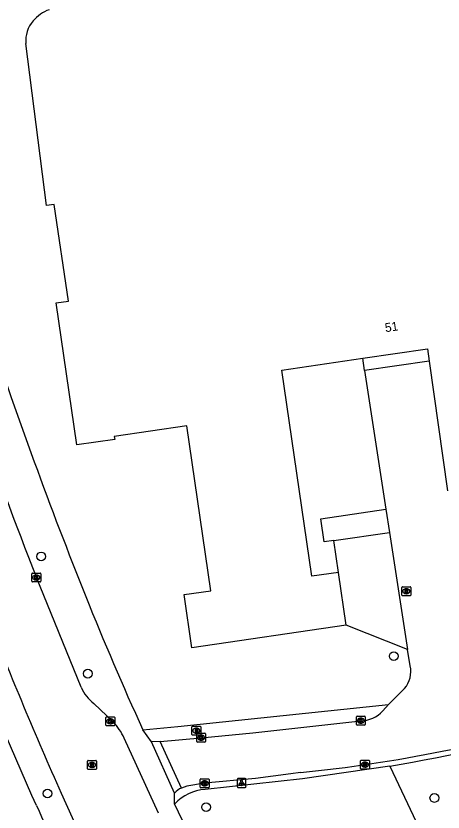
# Model space of a CAD drawing. Extents: x 159503 to 160347, y 382525 to 383272.
# Drawn here: x 159637.5 to 159685.5, y 382615.1 to 382704.5 of the extents above; entities that cross this region are included whole.
import ezdxf

# ---------------------------------------------------------------- set-up
doc = ezdxf.new("R2010")
doc.units = 0
for name, color, linetype in [('IMGEO_Boom', 7, 'Continuous'), ('IMGEO_Brandkraan', 7, 'Continuous'), ('IMGEO_Groenvoorziening', 7, 'Continuous'), ('IMGEO_Kolk', 7, 'Continuous'), ('IMGEO_Lichtpunt', 7, 'Continuous'), ('IMGEO_Pand', 7, 'Continuous'), ('IMGEO_Pand_nummerreeks', 7, 'Continuous'), ('IMGEO_Parkeervlak_open', 7, 'Continuous'), ('IMGEO_Rijbaan_lokaal_open', 7, 'Continuous'), ('IMGEO_Rijbaan_regionaal_gesloten', 7, 'Continuous'), ('IMGEO_Rioolput', 7, 'Continuous'), ('IMGEO_Voetpad_open', 7, 'Continuous')]:
    doc.layers.add(name, color=color, linetype=linetype)

msp = doc.modelspace()

# ---------------------------------------------------------------- linework, layer by layer
at = {"layer": 'IMGEO_Boom'}
for centre in [(159640.39, 382643.791), (159679.978, 382632.569), (159645.632, 382630.613), (159641.094, 382617.148), (159684.542, 382616.644), (159658.898, 382615.617)]:
    msp.add_circle(centre, 0.489, dxfattribs=at)
at = {"layer": 'IMGEO_Brandkraan'}
for p, q in [((159657.311, 382623.78), (159657.311, 382624.632)), ((159657.386, 382624.706), (159658.238, 382624.706)), ((159657.799, 382624.486), (159657.824, 382624.486)), ((159658.312, 382624.632), (159658.312, 382623.78)), ((159658.238, 382623.706), (159657.386, 382623.706)), ((159657.822, 382623.926), (159657.797, 382623.926))]:
    msp.add_line(p, q, dxfattribs=at)
for points in [[(159657.311, 382623.78), (159657.311, 382624.632)], [(159657.386, 382624.706), (159658.238, 382624.706)], [(159657.659, 382624.406), (159657.659, 382624.006), (159657.872, 382624.006)], [(159657.89, 382624.406), (159657.659, 382624.406)], [(159658.312, 382624.632), (159658.312, 382623.78)], [(159658.238, 382623.706), (159657.386, 382623.706)], [(159657.838, 382624.325), (159657.784, 382624.325), (159657.784, 382624.249)], [(159657.784, 382624.249), (159657.837, 382624.249)], [(159657.846, 382624.173), (159657.784, 382624.173), (159657.784, 382624.092)], [(159657.784, 382624.092), (159657.846, 382624.092)]]:
    msp.add_lwpolyline(points, dxfattribs=at)
for centre, radius, start, end in [((159657.388, 382624.63), 0.0765, 91.55205, 178.44795), ((159657.388, 382624.63), 0.0765, 91.55205, 178.44795), ((159657.894, 382624.261), 0.145, 59.4692, 91.53667), ((159657.919, 382624.308), 0.0922, 285.51372, 58.15012), ((159658.236, 382624.63), 0.0765, 1.55205, 88.44795), ((159658.236, 382624.63), 0.0765, 1.55205, 88.44795), ((159657.388, 382623.782), 0.0765, 181.55205, 268.44795), ((159657.388, 382623.782), 0.0765, 181.55205, 268.44795), ((159657.839, 382624.287), 0.0379, 267.82845, 90.93552), ((159657.847, 382624.132), 0.0404, 269.87594, 90.50774), ((159657.878, 382624.257), 0.251, 268.66757, 293.53466), ((159657.924, 382624.116), 0.105, 301.31148, 78.98903), ((159658.236, 382623.782), 0.0765, 271.55205, 358.44795), ((159658.236, 382623.782), 0.0765, 271.55205, 358.44795)]:
    msp.add_arc(centre, radius, start, end, dxfattribs=at)
for centre, major_axis, ratio, start_param, end_param in [((159657.798, 382624.206), (-0.387, 0.002), 0.722429, 4.712389, 7.853982), ((159657.823, 382624.206), (-0.39, 0.002), 0.717154, 1.570796, 4.712389)]:
    msp.add_ellipse(centre, major_axis=major_axis, ratio=ratio, start_param=start_param, end_param=end_param, dxfattribs=at)
at = {"layer": 'IMGEO_Groenvoorziening'}
msp.add_lwpolyline([(159679.532, 382620.228), (159692.346, 382593.146)], dxfattribs=at)
at = {"layer": 'IMGEO_Kolk'}
for p, q in [((159639.342, 382640.986), (159639.342, 382641.838)), ((159639.417, 382641.912), (159640.269, 382641.912)), ((159639.83, 382641.692), (159639.855, 382641.692)), ((159640.343, 382641.838), (159640.343, 382640.986)), ((159640.269, 382640.912), (159639.417, 382640.912)), ((159639.853, 382641.132), (159639.828, 382641.132)), ((159647.643, 382624.838), (159647.643, 382625.69)), ((159647.718, 382625.764), (159648.57, 382625.764)), ((159648.131, 382625.544), (159648.156, 382625.544)), ((159648.644, 382625.69), (159648.644, 382624.838)), ((159675.781, 382624.903), (159675.781, 382625.755)), ((159675.856, 382625.829), (159676.708, 382625.829)), ((159676.269, 382625.609), (159676.294, 382625.609)), ((159676.782, 382625.755), (159676.782, 382624.903)), ((159648.57, 382624.764), (159647.718, 382624.764)), ((159648.154, 382624.984), (159648.129, 382624.984)), ((159676.708, 382624.829), (159675.856, 382624.829)), ((159676.292, 382625.049), (159676.267, 382625.049)), ((159657.851, 382622.989), (159657.851, 382623.841)), ((159657.926, 382623.915), (159658.778, 382623.915)), ((159658.339, 382623.695), (159658.364, 382623.695)), ((159658.852, 382623.841), (159658.852, 382622.989)), ((159658.778, 382622.915), (159657.926, 382622.915)), ((159658.362, 382623.135), (159658.337, 382623.135)), ((159676.249, 382619.969), (159676.249, 382620.821)), ((159676.324, 382620.895), (159677.176, 382620.895)), ((159677.25, 382620.821), (159677.25, 382619.969)), ((159676.76, 382620.115), (159676.735, 382620.115)), ((159676.737, 382620.675), (159676.762, 382620.675)), ((159677.176, 382619.895), (159676.324, 382619.895)), ((159658.234, 382617.865), (159658.234, 382618.717)), ((159658.309, 382618.791), (159659.161, 382618.791)), ((159658.722, 382618.571), (159658.747, 382618.571)), ((159659.235, 382618.717), (159659.235, 382617.865)), ((159659.161, 382617.791), (159658.309, 382617.791)), ((159658.745, 382618.011), (159658.72, 382618.011))]:
    msp.add_line(p, q, dxfattribs=at)
for points in [[(159639.342, 382640.986), (159639.342, 382641.838)], [(159639.417, 382641.912), (159640.269, 382641.912)], [(159639.663, 382641.612), (159639.786, 382641.612), (159639.786, 382641.461), (159639.916, 382641.612), (159640.08, 382641.612), (159639.934, 382641.461), (159640.087, 382641.212), (159639.935, 382641.212), (159639.85, 382641.376), (159639.786, 382641.309), (159639.786, 382641.212), (159639.663, 382641.212), (159639.663, 382641.612)], [(159640.343, 382641.838), (159640.343, 382640.986)], [(159640.269, 382640.912), (159639.417, 382640.912)], [(159647.643, 382624.838), (159647.643, 382625.69)], [(159647.718, 382625.764), (159648.57, 382625.764)], [(159647.964, 382625.464), (159648.087, 382625.464), (159648.087, 382625.313), (159648.217, 382625.464), (159648.381, 382625.464), (159648.235, 382625.313), (159648.388, 382625.064), (159648.236, 382625.064), (159648.151, 382625.228), (159648.087, 382625.161), (159648.087, 382625.064), (159647.964, 382625.064), (159647.964, 382625.464)], [(159648.644, 382625.69), (159648.644, 382624.838)], [(159675.781, 382624.903), (159675.781, 382625.755)], [(159675.856, 382625.829), (159676.708, 382625.829)], [(159676.102, 382625.529), (159676.225, 382625.529), (159676.225, 382625.378), (159676.355, 382625.529), (159676.519, 382625.529), (159676.373, 382625.378), (159676.526, 382625.129), (159676.374, 382625.129), (159676.289, 382625.293), (159676.225, 382625.226), (159676.225, 382625.129), (159676.102, 382625.129), (159676.102, 382625.529)], [(159676.782, 382625.755), (159676.782, 382624.903)], [(159648.57, 382624.764), (159647.718, 382624.764)], [(159676.708, 382624.829), (159675.856, 382624.829)], [(159657.851, 382622.989), (159657.851, 382623.841)], [(159657.926, 382623.915), (159658.778, 382623.915)], [(159658.172, 382623.615), (159658.295, 382623.615), (159658.295, 382623.464), (159658.425, 382623.615), (159658.589, 382623.615), (159658.443, 382623.464), (159658.596, 382623.215), (159658.444, 382623.215), (159658.359, 382623.379), (159658.295, 382623.312), (159658.295, 382623.215), (159658.172, 382623.215), (159658.172, 382623.615)], [(159658.852, 382623.841), (159658.852, 382622.989)], [(159658.778, 382622.915), (159657.926, 382622.915)], [(159676.249, 382619.969), (159676.249, 382620.821)], [(159676.324, 382620.895), (159677.176, 382620.895)], [(159677.25, 382620.821), (159677.25, 382619.969)], [(159676.57, 382620.595), (159676.693, 382620.595), (159676.693, 382620.444), (159676.823, 382620.595), (159676.987, 382620.595), (159676.841, 382620.444), (159676.994, 382620.195), (159676.842, 382620.195), (159676.757, 382620.359), (159676.693, 382620.292), (159676.693, 382620.195), (159676.57, 382620.195), (159676.57, 382620.595)], [(159677.176, 382619.895), (159676.324, 382619.895)], [(159658.234, 382617.865), (159658.234, 382618.717)], [(159658.309, 382618.791), (159659.161, 382618.791)], [(159658.555, 382618.491), (159658.678, 382618.491), (159658.678, 382618.34), (159658.808, 382618.491), (159658.972, 382618.491), (159658.826, 382618.34), (159658.979, 382618.091), (159658.827, 382618.091), (159658.742, 382618.255), (159658.678, 382618.188), (159658.678, 382618.091), (159658.555, 382618.091), (159658.555, 382618.491)], [(159659.235, 382618.717), (159659.235, 382617.865)], [(159659.161, 382617.791), (159658.309, 382617.791)]]:
    msp.add_lwpolyline(points, dxfattribs=at)
for centre, start, end in [((159639.419, 382641.836), 91.55205, 178.44795), ((159639.419, 382641.836), 91.55205, 178.44795), ((159640.267, 382641.836), 1.55205, 88.44795), ((159640.267, 382641.836), 1.55205, 88.44795), ((159639.419, 382640.988), 181.55205, 268.44795), ((159639.419, 382640.988), 181.55205, 268.44795), ((159640.267, 382640.988), 271.55205, 358.44795), ((159640.267, 382640.988), 271.55205, 358.44795), ((159647.72, 382625.688), 91.55205, 178.44795), ((159647.72, 382625.688), 91.55205, 178.44795), ((159648.568, 382625.688), 1.55205, 88.44795), ((159648.568, 382625.688), 1.55205, 88.44795), ((159675.858, 382625.753), 91.55205, 178.44795), ((159675.858, 382625.753), 91.55205, 178.44795), ((159676.706, 382625.753), 1.55205, 88.44795), ((159676.706, 382625.753), 1.55205, 88.44795), ((159647.72, 382624.84), 181.55205, 268.44795), ((159647.72, 382624.84), 181.55205, 268.44795), ((159648.568, 382624.84), 271.55205, 358.44795), ((159648.568, 382624.84), 271.55205, 358.44795), ((159675.858, 382624.905), 181.55205, 268.44795), ((159675.858, 382624.905), 181.55205, 268.44795), ((159676.706, 382624.905), 271.55205, 358.44795), ((159676.706, 382624.905), 271.55205, 358.44795), ((159657.928, 382623.839), 91.55205, 178.44795), ((159657.928, 382623.839), 91.55205, 178.44795), ((159658.776, 382623.839), 1.55205, 88.44795), ((159658.776, 382623.839), 1.55205, 88.44795), ((159657.928, 382622.991), 181.55205, 268.44795), ((159657.928, 382622.991), 181.55205, 268.44795), ((159658.776, 382622.991), 271.55205, 358.44795), ((159658.776, 382622.991), 271.55205, 358.44795), ((159676.326, 382620.819), 91.55205, 178.44795), ((159676.326, 382620.819), 91.55205, 178.44795), ((159677.174, 382620.819), 1.55205, 88.44795), ((159677.174, 382620.819), 1.55205, 88.44795), ((159676.326, 382619.971), 181.55205, 268.44795), ((159676.326, 382619.971), 181.55205, 268.44795), ((159677.174, 382619.971), 271.55205, 358.44795), ((159677.174, 382619.971), 271.55205, 358.44795), ((159658.311, 382618.715), 91.55205, 178.44795), ((159658.311, 382618.715), 91.55205, 178.44795), ((159659.159, 382618.715), 1.55205, 88.44795), ((159659.159, 382618.715), 1.55205, 88.44795), ((159658.311, 382617.867), 181.55205, 268.44795), ((159658.311, 382617.867), 181.55205, 268.44795), ((159659.159, 382617.867), 271.55205, 358.44795), ((159659.159, 382617.867), 271.55205, 358.44795)]:
    msp.add_arc(centre, 0.0765, start, end, dxfattribs=at)
for centre, major_axis, ratio, start_param, end_param in [((159639.829, 382641.412), (-0.387, 0.002), 0.722429, 4.712389, 7.853982), ((159639.854, 382641.412), (-0.39, 0.002), 0.717154, 1.570796, 4.712389), ((159648.13, 382625.264), (-0.387, 0.002), 0.722429, 4.712389, 7.853982), ((159648.155, 382625.264), (-0.39, 0.002), 0.717154, 1.570796, 4.712389), ((159676.268, 382625.329), (-0.387, 0.002), 0.722429, 4.712389, 7.853982), ((159676.293, 382625.329), (-0.39, 0.002), 0.717154, 1.570796, 4.712389), ((159658.338, 382623.415), (-0.387, 0.002), 0.722429, 4.712389, 7.853982), ((159658.363, 382623.415), (-0.39, 0.002), 0.717154, 1.570796, 4.712389), ((159676.736, 382620.395), (-0.387, 0.002), 0.722429, 4.712389, 7.853982), ((159676.761, 382620.395), (-0.39, 0.002), 0.717154, 1.570796, 4.712389), ((159658.721, 382618.291), (-0.387, 0.002), 0.722429, 4.712389, 7.853982), ((159658.746, 382618.291), (-0.39, 0.002), 0.717154, 1.570796, 4.712389)]:
    msp.add_ellipse(centre, major_axis=major_axis, ratio=ratio, start_param=start_param, end_param=end_param, dxfattribs=at)
at = {"layer": 'IMGEO_Lichtpunt'}
for p, q in [((159662.391, 382618.731), (159662.391, 382617.924)), ((159662.391, 382618.731), (159662.391, 382617.924)), ((159663.293, 382618.826), (159662.485, 382618.826)), ((159663.293, 382618.826), (159662.485, 382618.826)), ((159663.387, 382617.924), (159663.387, 382618.731)), ((159663.387, 382617.924), (159663.387, 382618.731)), ((159662.485, 382617.83), (159663.293, 382617.83)), ((159662.485, 382617.83), (159663.293, 382617.83))]:
    msp.add_line(p, q, dxfattribs=at)
for points in [[(159662.765, 382618.395), (159662.804, 382618.367), (159662.616, 382618.105), (159662.578, 382618.132), (159662.765, 382618.395)], [(159662.867, 382618.347), (159662.914, 382618.347), (159662.914, 382618.025), (159662.867, 382618.025), (159662.867, 382618.347)], [(159662.977, 382618.367), (159663.015, 382618.394), (159663.202, 382618.132), (159663.163, 382618.104), (159662.977, 382618.367)]]:
    msp.add_lwpolyline(points, dxfattribs=at)
msp.add_circle((159662.89, 382618.529), 0.0994, dxfattribs=at)
for centre, start, end in [((159662.485, 382618.731), 90, 180), ((159662.485, 382618.731), 90, 180), ((159663.293, 382618.731), 0, 90), ((159663.293, 382618.731), 0, 90), ((159662.485, 382617.924), 180, 270), ((159662.485, 382617.924), 180, 270), ((159663.293, 382617.924), 270, 0), ((159663.293, 382617.924), 270, 360)]:
    msp.add_arc(centre, 0.0946, start, end, dxfattribs=at)
at = {"layer": 'IMGEO_Pand'}
for points in [[(159674.654, 382636.047), (159657.299, 382633.515), (159656.427, 382639.494), (159659.453, 382639.936), (159656.75, 382658.455), (159648.598, 382657.265), (159648.647, 382656.927), (159644.395, 382656.307), (159642.066, 382672.269), (159643.442, 382672.47), (159641.857, 382683.335), (159640.997, 382683.21), (159638.66, 382701.423)], [(159676.502, 382666.054), (159683.769, 382667.115), (159683.967, 382665.716)], [(159673.787, 382641.988), (159670.783, 382641.55), (159667.4, 382664.726), (159676.502, 382666.054)], [(159683.967, 382665.716), (159686.027, 382651.138)], [(159674.654, 382636.047), (159673.787, 382641.988)]]:
    msp.add_lwpolyline(points, dxfattribs=at)
for centre, radius, start, end in [((159642.683, 382701.29), 4.164, 109.83892, 140.35503), ((159642.019, 382701.73), 3.373, 138.90336, 185.22388)]:
    msp.add_arc(centre, radius, start, end, dxfattribs=at)
at = {"layer": 'IMGEO_Parkeervlak_open'}
msp.add_lwpolyline([(159681.528, 382633.32), (159674.654, 382636.047)], dxfattribs=at)
at = {"layer": 'IMGEO_Rijbaan_lokaal_open'}
for points in [[(159683.967, 382665.716), (159676.706, 382664.657)], [(159676.706, 382664.657), (159679.103, 382649.082)], [(159679.103, 382649.082), (159679.504, 382646.476)], [(159679.504, 382646.476), (159681.528, 382633.32)], [(159644.858, 382629.099), (159639.842, 382641.412)], [(159681.844, 382631.497), (159681.528, 382633.32)], [(159679.397, 382627.147), (159681.206, 382628.947)], [(159648.463, 382625.194), (159646.308, 382627.242)], [(159678.741, 382626.446), (159679.397, 382627.147)], [(159653.754, 382622.997), (159658.352, 382623.413), (159664.14, 382623.954), (159676.278, 382625.327)], [(159653.555, 382614.944), (159649.718, 382623.375)], [(159653.754, 382622.997), (159652.76, 382622.944)], [(159655.372, 382617.19), (159652.76, 382622.944)], [(159656.147, 382617.762), (159653.754, 382622.997)], [(159669.525, 382619.5), (159668.421, 382619.359), (159664.462, 382618.848), (159658.735, 382618.292), (159656.758, 382617.98), (159656.147, 382617.762)], [(159642.633, 382617.174), (159647.401, 382606.58), (159647.894, 382605.529)]]:
    msp.add_lwpolyline(points, dxfattribs=at)
for centre, radius, start, end in [((160237.548, 382874.244), 641.454, 199.534476, 201.282993), ((160085.442, 382814.192), 484.661, 201.46766, 203.98563), ((159678.887, 382630.882), 3.02, 320.15553, 11.75084), ((159649.602, 382631.308), 5.233, 204.97391, 230.99361), ((159676.312, 382628.521), 3.195, 269.38251, 319.48437), ((159652.145, 382789.166), 170.553, 275.84878, 286.66059), ((159642.994, 382620.078), 7.489, 26.11845, 43.08821), ((159656.953, 382615.859), 2.067, 112.95278, 139.90665)]:
    msp.add_arc(centre, radius, start, end, dxfattribs=at)
at = {"layer": 'IMGEO_Rijbaan_regionaal_gesloten'}
msp.add_lwpolyline([(159639.855, 382615.784), (159639.351, 382616.939), (159631.979, 382633.823), (159631.64, 382634.537), (159631.301, 382635.251)], dxfattribs=at)
msp.add_arc((159974.799, 382766.166), 367.154, 204.17893, 207.66337, dxfattribs=at)
at = {"layer": 'IMGEO_Rioolput'}
for p, q in [((159680.895, 382639.449), (159680.895, 382640.301)), ((159680.97, 382640.375), (159681.822, 382640.375)), ((159681.406, 382639.595), (159681.381, 382639.595)), ((159681.383, 382640.155), (159681.408, 382640.155)), ((159681.896, 382640.301), (159681.896, 382639.449)), ((159681.822, 382639.375), (159680.97, 382639.375)), ((159645.664, 382620.862), (159646.516, 382620.862)), ((159645.589, 382619.936), (159645.589, 382620.788)), ((159646.1, 382620.082), (159646.075, 382620.082)), ((159646.077, 382620.642), (159646.102, 382620.642)), ((159646.59, 382620.788), (159646.59, 382619.936)), ((159646.516, 382619.862), (159645.664, 382619.862))]:
    msp.add_line(p, q, dxfattribs=at)
for points in [[(159680.895, 382639.449), (159680.895, 382640.301)], [(159680.97, 382640.375), (159681.822, 382640.375)], [(159681.484, 382640.073), (159681.232, 382640.075), (159681.232, 382639.675)], [(159681.232, 382639.675), (159681.356, 382639.675), (159681.356, 382639.837), (159681.367, 382639.837)], [(159681.41, 382639.994), (159681.356, 382639.994), (159681.356, 382639.913)], [(159681.356, 382639.913), (159681.408, 382639.913)], [(159681.414, 382639.808), (159681.485, 382639.675), (159681.625, 382639.675), (159681.56, 382639.801)], [(159681.896, 382640.301), (159681.896, 382639.449)], [(159681.822, 382639.375), (159680.97, 382639.375)], [(159645.664, 382620.862), (159646.516, 382620.862)], [(159645.589, 382619.936), (159645.589, 382620.788)], [(159646.178, 382620.56), (159645.926, 382620.562), (159645.926, 382620.162)], [(159645.926, 382620.162), (159646.05, 382620.162), (159646.05, 382620.324), (159646.061, 382620.324)], [(159646.104, 382620.481), (159646.05, 382620.481), (159646.05, 382620.4)], [(159646.05, 382620.4), (159646.102, 382620.4)], [(159646.108, 382620.295), (159646.179, 382620.162), (159646.319, 382620.162), (159646.254, 382620.288)], [(159646.59, 382620.788), (159646.59, 382619.936)], [(159646.516, 382619.862), (159645.664, 382619.862)]]:
    msp.add_lwpolyline(points, dxfattribs=at)
for centre, radius, start, end in [((159680.972, 382640.299), 0.0765, 91.55205, 178.44795), ((159680.972, 382640.299), 0.0765, 91.55205, 178.44795), ((159681.366, 382639.784), 0.0533, 26.02933, 88.69889), ((159681.392, 382640.102), 0.19, 274.7715, 282.96867), ((159681.416, 382639.898), 0.0964, 77.00612, 93.18647), ((159681.43, 382639.955), 0.0378, 276.66336, 79.67722), ((159681.483, 382639.963), 0.109, 350.36119, 89.41601), ((159681.481, 382639.963), 0.112, 277.58423, 350.98172), ((159681.465, 382639.748), 0.108, 29.51342, 73.79051), ((159681.82, 382640.299), 0.0765, 1.55205, 88.44795), ((159681.82, 382640.299), 0.0765, 1.55205, 88.44795), ((159680.972, 382639.451), 0.0765, 181.55205, 268.44795), ((159680.972, 382639.451), 0.0765, 181.55205, 268.44795), ((159681.82, 382639.451), 0.0765, 271.55205, 358.44795), ((159681.82, 382639.451), 0.0765, 271.55205, 358.44795), ((159645.666, 382620.786), 0.0765, 91.55205, 178.44795), ((159645.666, 382620.786), 0.0765, 91.55205, 178.44795), ((159646.514, 382620.786), 0.0765, 1.55205, 88.44795), ((159646.514, 382620.786), 0.0765, 1.55205, 88.44795), ((159645.666, 382619.938), 0.0765, 181.55205, 268.44795), ((159645.666, 382619.938), 0.0765, 181.55205, 268.44795), ((159646.06, 382620.271), 0.0533, 26.02933, 88.69889), ((159646.086, 382620.589), 0.19, 274.7715, 282.96867), ((159646.11, 382620.385), 0.0964, 77.00612, 93.18647), ((159646.124, 382620.442), 0.0378, 276.66336, 79.67722), ((159646.177, 382620.45), 0.109, 350.36119, 89.41601), ((159646.175, 382620.45), 0.112, 277.58423, 350.98172), ((159646.159, 382620.235), 0.108, 29.51342, 73.79051), ((159646.514, 382619.938), 0.0765, 271.55205, 358.44795), ((159646.514, 382619.938), 0.0765, 271.55205, 358.44795)]:
    msp.add_arc(centre, radius, start, end, dxfattribs=at)
for centre, major_axis, ratio, start_param, end_param in [((159681.382, 382639.875), (-0.387, 0.002), 0.722429, 4.712389, 7.853982), ((159681.407, 382639.875), (-0.39, 0.002), 0.717154, 1.570796, 4.712389), ((159646.076, 382620.362), (-0.387, 0.002), 0.722429, 4.712389, 7.853982), ((159646.101, 382620.362), (-0.39, 0.002), 0.717154, 1.570796, 4.712389)]:
    msp.add_ellipse(centre, major_axis=major_axis, ratio=ratio, start_param=start_param, end_param=end_param, dxfattribs=at)
at = {"layer": 'IMGEO_Voetpad_open'}
for points in [[(159627.166, 382691.73), (159633.264, 382672.724), (159636.993, 382661.627), (159639.603, 382654.41)], [(159676.706, 382664.657), (159676.502, 382666.054)], [(159673.259, 382645.569), (159672.175, 382645.412), (159671.796, 382648.021), (159679.103, 382649.082)], [(159673.259, 382645.569), (159679.504, 382646.476)], [(159673.787, 382641.988), (159673.259, 382645.569)], [(159651.799, 382624.316), (159655.72, 382624.685), (159679.397, 382627.147)], [(159652.76, 382622.944), (159651.799, 382624.316)], [(159679.532, 382620.228), (159669.727, 382618.786), (159658.805, 382617.605)], [(159655.373, 382615.968), (159655.372, 382617.19)], [(159655.373, 382615.968), (159660.451, 382605.328), (159666.118, 382593.788)]]:
    msp.add_lwpolyline(points, dxfattribs=at)
for centre, radius, start, end in [((160108.471, 382825.391), 499.071, 200.03529, 201.89663), ((159957.714, 382763.975), 336.287, 201.76661, 204.53806), ((159641.583, 382844.176), 227.14, 279.61758, 284.88444), ((159659.089, 382612.593), 5.02, 93.24617, 137.75438)]:
    msp.add_arc(centre, radius, start, end, dxfattribs=at)

# ---------------------------------------------------------------- texts
at = {"layer": 'IMGEO_Pand_nummerreeks'}
msp.add_text('51', height=1, rotation=8.30789, dxfattribs=at).set_placement((159679.066, 382668.975))

doc.saveas('drawing.dxf')
